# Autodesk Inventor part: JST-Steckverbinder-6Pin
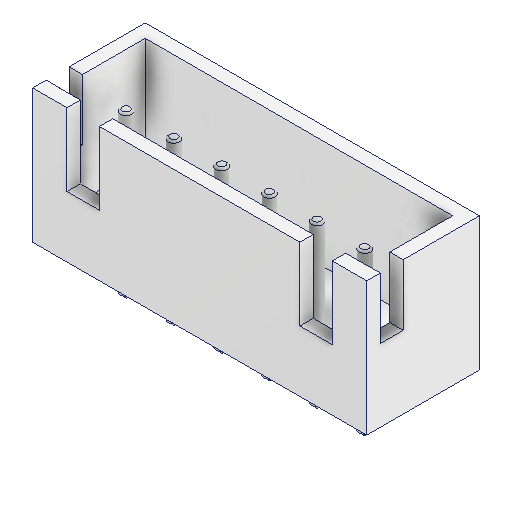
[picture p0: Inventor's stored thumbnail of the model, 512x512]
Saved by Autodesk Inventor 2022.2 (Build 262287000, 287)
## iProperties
Created: 2024-09
Part Number: JST-Steckverbinder-6Pin
Material: Generico
Document SubType Name: Modeling
Designer: 18907419
Density: 1 g/cm^3
Appearance: Default
Author: 18907419
Revision Number: ANY
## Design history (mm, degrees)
feature "Verrundung1"
node "Solido1"
